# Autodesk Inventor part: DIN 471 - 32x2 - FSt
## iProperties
Created: 2006-06
Material: FSt
Description: Sicherungsring
Vendor: Autodesk Inc.
Document SubType Name: Modeling
Standard: DIN 471
Designer: I.Baliuc
Standards Organization: DIN
Language: de-DE
Size Designation: 32 x 2
Categories: <MemberInstance Version="R10.0.0"><Categories><Category DisplayName="Wellenteile" InternalName="7f7aeb1f-a693-4053-b835-cee3144e0d98" Mnemonic="SHFT"><Category
Density: 7.85 g/cm^3
Mass: 6.90298 g
Surface Area: 13.7179 cm^2
Volume: 0.879361 cm^3
Abmessung: 32 x 2
Author: T.Messerschmitt
Comments: DIN 471 - 32 x 2
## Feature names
1. Körper [Extrusion]
